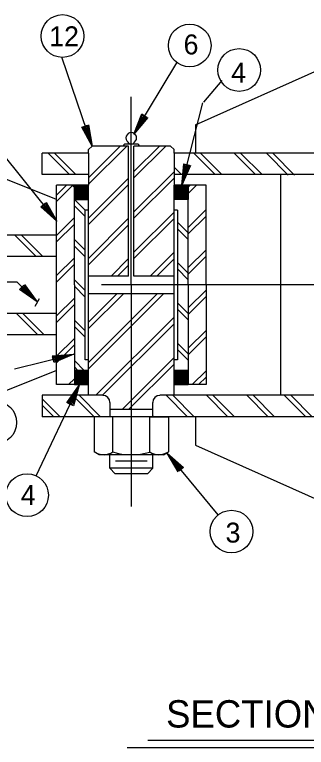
# Model space of a CAD drawing. Extents: x 0.1 to 13.5, y 0.1 to 9.5.
# Drawn here: x 7.902 to 8.756, y 5.682 to 7.825 of the extents above; entities that cross this region are included whole.
import ezdxf

# ---------------------------------------------------------------- set-up
doc = ezdxf.new("R2010")
doc.units = 0
for name, color, linetype in [('Level 2', 7, 'Continuous'), ('Level 25', 7, 'Continuous'), ('Level 3', 7, 'Continuous'), ('Level 50', 7, 'Continuous')]:
    doc.layers.add(name, color=color, linetype=linetype)

msp = doc.modelspace()

# ---------------------------------------------------------------- linework, layer by layer
at = {"layer": 'Level 2'}
for p, q in [((8.2434, 7.0344), (8.2434, 7.5849)), ((8.4309, 7.5031), (8.4309, 7.4198)), ((8.1288, 7.4406), (8.1184, 7.4302)), ((8.2356, 7.4406), (8.1288, 7.4406)), ((8.2202, 7.4406), (8.2202, 7.4416)), ((8.2624, 7.4458), (8.2244, 7.4458)), ((8.2356, 7.0604), (8.2356, 7.4406)), ((8.2434, 7.4458), (8.2434, 7.4458)), ((8.2434, 7.4458), (8.2434, 7.4458)), ((8.2512, 7.0604), (8.2512, 7.4406)), ((8.358, 7.4406), (8.2512, 7.4406)), ((8.2665, 7.4406), (8.2665, 7.4416)), ((8.358, 7.4406), (8.3684, 7.4302)), ((7.983, 7.3573), (7.983, 7.4198)), ((8.1184, 7.4198), (7.983, 7.4198)), ((8.1184, 7.4198), (8.1184, 7.4302)), ((8.1184, 7.4198), (8.1184, 7.3261)), ((8.3684, 7.4198), (8.3684, 7.4302)), ((8.3684, 7.4198), (8.3684, 7.3261)), ((9.0976, 7.4198), (8.3684, 7.4198)), ((8.1184, 7.3573), (7.983, 7.3573)), ((9.0976, 7.3573), (8.3684, 7.3573)), ((8.6809, 6.7115), (8.6809, 7.3573)), ((8.0247, 6.7427), (8.0247, 7.3261)), ((8.1184, 7.3261), (8.0247, 7.3261)), ((8.0768, 7.0344), (8.0768, 7.3261)), ((8.1184, 6.7115), (8.1184, 7.3261)), ((8.4622, 7.3261), (8.3684, 7.3261)), ((8.3684, 6.7115), (8.3684, 7.3261)), ((8.4101, 7.0344), (8.4101, 7.3261)), ((8.4622, 7.0344), (8.4622, 7.3261)), ((8.1184, 7.2844), (8.0768, 7.2844)), ((8.4101, 7.2844), (8.3684, 7.2844)), ((8.108, 6.8156), (8.108, 7.2531)), ((8.1184, 7.2531), (8.108, 7.2531)), ((8.3788, 7.2531), (8.3684, 7.2531)), ((8.3788, 7.2531), (8.3788, 6.8156)), ((8.0247, 7.1802), (7.4186, 7.1802)), ((8.0247, 7.1177), (7.4186, 7.1177)), ((8.2356, 7.0604), (8.1184, 7.0604)), ((8.3684, 7.0604), (8.2512, 7.0604)), ((8.0768, 7.0344), (8.0768, 6.7427)), ((10.1049, 7.0344), (8.1558, 7.0344)), ((8.2434, 7.0344), (8.2434, 6.3864)), ((8.4101, 7.0344), (8.4101, 6.7427)), ((8.4622, 7.0344), (8.4622, 6.7427)), ((8.3684, 7.0083), (8.1184, 7.0083)), ((8.0247, 6.9511), (7.4186, 6.9511)), ((8.0247, 6.8886), (7.4186, 6.8886)), ((8.1184, 6.8156), (8.108, 6.8156)), ((8.3788, 6.8156), (8.3684, 6.8156)), ((8.1184, 6.7844), (8.0768, 6.7844)), ((8.4101, 6.7844), (8.3684, 6.7844)), ((8.1184, 6.7427), (8.0247, 6.7427)), ((8.4622, 6.7427), (8.3684, 6.7427)), ((7.983, 6.7115), (7.983, 6.649)), ((8.1601, 6.7115), (7.983, 6.7115)), ((9.0976, 6.7115), (8.3268, 6.7115)), ((8.1809, 6.6906), (8.1809, 6.649)), ((8.3059, 6.6906), (8.3059, 6.649)), ((8.3059, 6.6698), (8.1809, 6.6698)), ((9.0976, 6.649), (7.983, 6.649)), ((8.3997, 6.649), (8.0872, 6.649)), ((8.1351, 6.649), (8.1351, 6.5461)), ((8.1892, 6.5459), (8.1892, 6.649)), ((8.2969, 6.649), (8.3518, 6.649)), ((8.2977, 6.5459), (8.2977, 6.649)), ((8.3518, 6.649), (8.3518, 6.5461)), ((8.4309, 6.649), (8.4309, 6.5656)), ((8.1496, 6.5377), (8.1351, 6.5461)), ((8.3373, 6.5377), (8.1496, 6.5377)), ((8.1807, 6.498), (8.1807, 6.5377)), ((8.3061, 6.498), (8.3061, 6.5377)), ((8.3373, 6.5377), (8.3518, 6.5461)), ((8.2903, 6.519), (8.197, 6.519)), ((8.1807, 6.498), (8.1963, 6.4823)), ((8.3061, 6.498), (8.1807, 6.498)), ((8.3061, 6.498), (8.2905, 6.4823)), ((8.2905, 6.4823), (8.1963, 6.4823)), ((8.2905, 6.4823), (8.1963, 6.4823)), ((8.2903, 6.4823), (8.197, 6.4823))]:
    msp.add_line(p, q, dxfattribs=at)
for points in [[(8.1184, 7.3289), (8.2302, 7.4406)], [(8.1184, 7.3478), (8.2113, 7.4406)], [(8.2512, 7.3473), (8.3446, 7.4406)], [(8.2512, 7.3662), (8.3257, 7.4406)], [(8.0624, 7.3573), (7.9999, 7.4198)], [(8.0812, 7.3573), (8.0187, 7.4198)], [(8.1184, 7.4191), (8.1177, 7.4198)], [(8.4892, 7.3573), (8.4267, 7.4198)], [(8.5081, 7.3573), (8.4456, 7.4198)], [(8.6071, 7.3573), (8.5446, 7.4198)], [(8.6259, 7.3573), (8.5634, 7.4198)], [(8.7024, 7.3559), (8.6399, 7.4184)], [(8.7024, 7.3559), (8.6399, 7.4184)], [(8.7212, 7.3559), (8.6587, 7.4184)], [(8.7212, 7.3559), (8.6587, 7.4184)], [(8.3902, 7.3573), (8.3684, 7.3791)], [(8.2512, 7.2483), (8.3684, 7.3655)], [(8.3714, 7.3573), (8.3684, 7.3602)], [(8.1184, 7.2299), (8.2356, 7.3471)], [(8.2512, 7.2295), (8.3684, 7.3467)], [(8.0247, 7.2783), (8.0724, 7.3261)], [(8.0247, 7.2972), (8.0536, 7.3261)], [(8.0768, 7.3193), (8.07, 7.3261)], [(8.0768, 7.3255), (8.1184, 7.3255)], [(8.0768, 7.3242), (8.1184, 7.3242)], [(8.0768, 7.323), (8.1184, 7.323)], [(8.0768, 7.3217), (8.1184, 7.3217)], [(8.0768, 7.3205), (8.1184, 7.3205)], [(8.0768, 7.3192), (8.1184, 7.3192)], [(8.0768, 7.318), (8.1184, 7.318)], [(8.0768, 7.3167), (8.1184, 7.3167)], [(8.0768, 7.3155), (8.1184, 7.3155)], [(8.0768, 7.3142), (8.1184, 7.3142)], [(8.0768, 7.313), (8.1184, 7.313)], [(8.0768, 7.3117), (8.1184, 7.3117)], [(8.0768, 7.3105), (8.1184, 7.3105)], [(8.0768, 7.3092), (8.1184, 7.3092)], [(8.0768, 7.308), (8.1184, 7.308)], [(8.1184, 7.211), (8.2356, 7.3282)], [(8.3684, 7.3255), (8.4101, 7.3255)], [(8.3684, 7.3243), (8.4101, 7.3243)], [(8.3684, 7.323), (8.4101, 7.323)], [(8.3684, 7.3218), (8.4101, 7.3218)], [(8.3684, 7.3205), (8.4101, 7.3205)], [(8.3684, 7.3193), (8.4101, 7.3193)], [(8.3684, 7.318), (8.4101, 7.318)], [(8.3684, 7.3168), (8.4101, 7.3168)], [(8.3684, 7.3155), (8.4101, 7.3155)], [(8.3684, 7.3143), (8.4101, 7.3143)], [(8.3684, 7.313), (8.4101, 7.313)], [(8.3684, 7.3118), (8.4101, 7.3118)], [(8.3684, 7.3105), (8.4101, 7.3105)], [(8.3684, 7.3093), (8.4101, 7.3093)], [(8.3684, 7.308), (8.4101, 7.308)], [(8.4101, 7.3018), (8.4344, 7.3261)], [(8.4101, 7.3206), (8.4155, 7.3261)], [(8.0768, 7.3067), (8.1184, 7.3067)], [(8.0768, 7.3055), (8.1184, 7.3055)], [(8.0768, 7.3042), (8.1184, 7.3042)], [(8.0768, 7.303), (8.1184, 7.303)], [(8.0768, 7.3017), (8.1184, 7.3017)], [(8.0768, 7.3005), (8.1184, 7.3005)], [(8.0768, 7.2992), (8.1184, 7.2992)], [(8.0768, 7.298), (8.1184, 7.298)], [(8.0768, 7.2967), (8.1184, 7.2967)], [(8.0768, 7.2955), (8.1184, 7.2955)], [(8.0768, 7.2942), (8.1184, 7.2942)], [(8.0768, 7.293), (8.1184, 7.293)], [(8.0768, 7.2917), (8.1184, 7.2917)], [(8.0768, 7.2905), (8.1184, 7.2905)], [(8.0768, 7.2892), (8.1184, 7.2892)], [(8.0768, 7.288), (8.1184, 7.288)], [(8.0768, 7.2867), (8.1184, 7.2867)], [(8.3684, 7.3068), (8.4101, 7.3068)], [(8.3684, 7.3055), (8.4101, 7.3055)], [(8.3684, 7.3043), (8.4101, 7.3043)], [(8.3684, 7.303), (8.4101, 7.303)], [(8.3684, 7.3018), (8.4101, 7.3018)], [(8.3684, 7.3005), (8.4101, 7.3005)], [(8.3684, 7.2993), (8.4101, 7.2993)], [(8.3684, 7.298), (8.4101, 7.298)], [(8.3684, 7.2968), (8.4101, 7.2968)], [(8.3684, 7.2955), (8.4101, 7.2955)], [(8.3684, 7.2943), (8.4101, 7.2943)], [(8.3684, 7.293), (8.4101, 7.293)], [(8.3684, 7.2918), (8.4101, 7.2918)], [(8.3684, 7.2905), (8.4101, 7.2905)], [(8.3684, 7.2893), (8.4101, 7.2893)], [(8.3684, 7.288), (8.4101, 7.288)], [(8.3684, 7.2868), (8.4101, 7.2868)], [(8.0768, 7.2855), (8.1184, 7.2855)], [(8.108, 7.2348), (8.0768, 7.266)], [(8.1085, 7.2531), (8.0772, 7.2844)], [(8.3684, 7.2855), (8.4101, 7.2855)], [(8.2512, 7.1305), (8.3684, 7.2477)], [(8.4101, 7.2028), (8.4622, 7.2549)], [(8.0247, 7.1793), (8.0768, 7.2314)], [(8.1184, 7.1121), (8.2356, 7.2292)], [(8.2512, 7.1116), (8.3684, 7.2288)], [(8.4101, 7.1839), (8.4622, 7.236)], [(8.0247, 7.1604), (8.0768, 7.2125)], [(8.1184, 7.0932), (8.2356, 7.2104)], [(8.4101, 7.1864), (8.3788, 7.2177)], [(7.9654, 7.1177), (7.9029, 7.1802)], [(7.9842, 7.1177), (7.9217, 7.1802)], [(8.4101, 7.1676), (8.3788, 7.1988)], [(8.108, 7.1358), (8.0768, 7.167)], [(8.108, 7.1169), (8.0768, 7.1481)], [(8.4101, 7.0849), (8.4622, 7.137)], [(8.299, 7.0604), (8.3684, 7.1298)], [(8.4101, 7.0661), (8.4622, 7.1182)], [(8.0247, 7.0615), (8.0768, 7.1136)], [(8.0247, 7.0426), (8.0768, 7.0947)], [(8.1847, 7.0604), (8.2356, 7.1114)], [(8.3179, 7.0604), (8.3684, 7.111)], [(8.4101, 7.0686), (8.3788, 7.0998)], [(8.2035, 7.0604), (8.2356, 7.0925)], [(8.4101, 7.0497), (8.3788, 7.081)], [(8.108, 7.0179), (8.0768, 7.0491)], [(8.108, 6.999), (8.0768, 7.0303)], [(8.1184, 6.7888), (8.3379, 7.0083)], [(8.1184, 6.9067), (8.2201, 7.0083)], [(8.1184, 6.8077), (8.3191, 7.0083)], [(8.1184, 6.9255), (8.2012, 7.0083)], [(8.4101, 6.9671), (8.4622, 7.0192)], [(8.0247, 6.9436), (8.0768, 6.9957)], [(8.4101, 6.9482), (8.4622, 7.0003)], [(8.0247, 6.9248), (8.0768, 6.9769)], [(8.4101, 6.9507), (8.3788, 6.982)], [(7.9697, 6.8886), (7.9072, 6.9511)], [(7.9886, 6.8886), (7.9261, 6.9511)], [(8.4101, 6.9319), (8.3788, 6.9631)], [(8.108, 6.9001), (8.0768, 6.9313)], [(8.1401, 6.7115), (8.3684, 6.9398)], [(8.108, 6.8812), (8.0768, 6.9124)], [(8.1589, 6.7115), (8.3684, 6.921)], [(8.4101, 6.8492), (8.4622, 6.9013)], [(8.4101, 6.8304), (8.4622, 6.8825)], [(8.0247, 6.8258), (8.0768, 6.8779)], [(8.0247, 6.8069), (8.0768, 6.859)], [(8.4101, 6.8329), (8.3788, 6.8641)], [(8.4101, 6.814), (8.3788, 6.8453)], [(8.2163, 6.6698), (8.3684, 6.822)], [(8.1058, 6.7844), (8.0768, 6.8134)], [(8.087, 6.7844), (8.0768, 6.7946)], [(8.2351, 6.6698), (8.3684, 6.8031)], [(8.0768, 6.7832), (8.1184, 6.7832)], [(8.0768, 6.7819), (8.1184, 6.7819)], [(8.0768, 6.7807), (8.1184, 6.7807)], [(8.0768, 6.7794), (8.1184, 6.7794)], [(8.0768, 6.7782), (8.1184, 6.7782)], [(8.0768, 6.7769), (8.1184, 6.7769)], [(8.0768, 6.7757), (8.1184, 6.7757)], [(8.0768, 6.7744), (8.1184, 6.7744)], [(8.0768, 6.7732), (8.1184, 6.7732)], [(8.3684, 6.7844), (8.4101, 6.7844)], [(8.3684, 6.7831), (8.4101, 6.7831)], [(8.3684, 6.7819), (8.4101, 6.7819)], [(8.3684, 6.7806), (8.4101, 6.7806)], [(8.3684, 6.7794), (8.4101, 6.7794)], [(8.3684, 6.7781), (8.4101, 6.7781)], [(8.3684, 6.7769), (8.4101, 6.7769)], [(8.3684, 6.7756), (8.4101, 6.7756)], [(8.3684, 6.7744), (8.4101, 6.7744)], [(8.3684, 6.7731), (8.4101, 6.7731)], [(8.4214, 6.7427), (8.4622, 6.7835)], [(8.0595, 6.7427), (8.0768, 6.76)], [(8.0768, 6.7719), (8.1184, 6.7719)], [(8.0768, 6.7707), (8.1184, 6.7707)], [(8.0768, 6.7694), (8.1184, 6.7694)], [(8.0768, 6.7682), (8.1184, 6.7682)], [(8.0768, 6.7669), (8.1184, 6.7669)], [(8.0768, 6.7657), (8.1184, 6.7657)], [(8.0768, 6.7644), (8.1184, 6.7644)], [(8.0768, 6.7632), (8.1184, 6.7632)], [(8.0768, 6.7619), (8.1184, 6.7619)], [(8.0768, 6.7607), (8.1184, 6.7607)], [(8.0768, 6.7594), (8.1184, 6.7594)], [(8.0768, 6.7582), (8.1184, 6.7582)], [(8.0768, 6.7569), (8.1184, 6.7569)], [(8.0768, 6.7557), (8.1184, 6.7557)], [(8.0768, 6.7544), (8.1184, 6.7544)], [(8.0768, 6.7532), (8.1184, 6.7532)], [(8.0768, 6.7519), (8.1184, 6.7519)], [(8.0768, 6.7507), (8.1184, 6.7507)], [(8.3684, 6.7719), (8.4101, 6.7719)], [(8.3684, 6.7706), (8.4101, 6.7706)], [(8.3684, 6.7694), (8.4101, 6.7694)], [(8.3684, 6.7681), (8.4101, 6.7681)], [(8.3684, 6.7669), (8.4101, 6.7669)], [(8.3684, 6.7656), (8.4101, 6.7656)], [(8.3684, 6.7644), (8.4101, 6.7644)], [(8.3684, 6.7631), (8.4101, 6.7631)], [(8.3684, 6.7619), (8.4101, 6.7619)], [(8.3684, 6.7606), (8.4101, 6.7606)], [(8.3684, 6.7594), (8.4101, 6.7594)], [(8.3684, 6.7581), (8.4101, 6.7581)], [(8.3684, 6.7569), (8.4101, 6.7569)], [(8.3684, 6.7556), (8.4101, 6.7556)], [(8.3684, 6.7544), (8.4101, 6.7544)], [(8.3684, 6.7531), (8.4101, 6.7531)], [(8.3684, 6.7519), (8.4101, 6.7519)], [(8.4403, 6.7427), (8.4622, 6.7646)], [(8.0768, 6.7494), (8.1184, 6.7494)], [(8.0768, 6.7482), (8.1184, 6.7482)], [(8.0768, 6.7469), (8.1184, 6.7469)], [(8.0768, 6.7457), (8.1184, 6.7457)], [(8.0768, 6.7444), (8.1184, 6.7444)], [(8.0768, 6.7432), (8.1184, 6.7432)], [(8.3684, 6.7506), (8.4101, 6.7506)], [(8.3684, 6.7494), (8.4101, 6.7494)], [(8.3684, 6.7481), (8.4101, 6.7481)], [(8.3684, 6.7469), (8.4101, 6.7469)], [(8.3684, 6.7456), (8.4101, 6.7456)], [(8.3684, 6.7444), (8.4101, 6.7444)], [(8.3684, 6.7431), (8.4101, 6.7431)], [(8.1343, 6.649), (8.0718, 6.7115)], [(8.1531, 6.649), (8.0906, 6.7115)], [(8.4083, 6.649), (8.3458, 6.7115)], [(8.4272, 6.649), (8.3647, 6.7115)], [(8.5262, 6.649), (8.4637, 6.7115)], [(8.545, 6.649), (8.4825, 6.7115)], [(8.644, 6.649), (8.5815, 6.7115)], [(8.6629, 6.649), (8.6004, 6.7115)], [(8.7537, 6.649), (8.6912, 6.7115)], [(8.7725, 6.649), (8.71, 6.7115)], [(8.0353, 6.649), (7.983, 6.7012)], [(8.0164, 6.649), (7.983, 6.6824)], [(8.3093, 6.649), (8.3059, 6.6524)]]:
    msp.add_lwpolyline(points, dxfattribs=at)
for points in [[(8.0768, 7.3261), (8.0768, 7.2844), (8.1184, 7.2844), (8.1184, 7.3261)], [(8.4101, 7.3261), (8.4101, 7.2844), (8.3684, 7.2844), (8.3684, 7.3261)], [(8.0768, 6.7844), (8.0768, 6.7427), (8.1184, 6.7427), (8.1184, 6.7844)], [(8.3684, 6.7844), (8.3684, 6.7427), (8.4101, 6.7427), (8.4101, 6.7844)]]:
    msp.add_lwpolyline(points, close=True, dxfattribs=at)
for centre, radius, start, end in [((8.2434, 7.4645), 0.0156, 306.8699, 233.1301), ((8.2244, 7.4416), 0.00417, 90, 180), ((8.2278, 7.4437), 0.0104, 11.771, 53.1301), ((8.2591, 7.4437), 0.0104, 126.8699, 168.229), ((8.2624, 7.4416), 0.00417, 0, 90), ((8.1601, 6.6906), 0.0208, 0, 90), ((8.3268, 6.6906), 0.0208, 90, 180), ((8.1625, 6.5847), 0.047, 239.7124, 304.511), ((8.2441, 6.7259), 0.1882, 253.0184, 286.4966), ((8.3243, 6.5847), 0.047, 235.489, 300.2876)]:
    msp.add_arc(centre, radius, start, end, dxfattribs=at)
at = {"layer": 'Level 25'}
for p, q in [((8.4309, 7.5031), (9.0143, 7.7636)), ((8.4554, 7.5694), (8.5091, 7.632)), ((8.0247, 7.2844), (7.502, 7.4927)), ((8.0256, 7.2212), (7.8111, 7.4878)), ((8.0247, 6.7844), (7.502, 6.5761)), ((8.4309, 6.5656), (9.0143, 6.3052))]:
    msp.add_line(p, q, dxfattribs=at)
at = {"layer": 'Level 3'}
for p, q in [((8.1288, 7.4406), (8.0397, 7.7006)), ((8.2509, 7.4758), (8.3766, 7.6843)), ((8.3913, 7.326), (8.4532, 7.5668)), ((8.2598, 7.4906), (8.2598, 7.4906)), ((8.2509, 7.4758), (8.2509, 7.4758)), ((8.1232, 7.457), (8.1232, 7.457)), ((8.1288, 7.4406), (8.1288, 7.4406)), ((8.3956, 7.3428), (8.3956, 7.3428)), ((8.3913, 7.326), (8.3913, 7.326)), ((7.8612, 7.0436), (7.9082, 7.0436)), ((7.9082, 7.0436), (7.9684, 6.9853)), ((7.956, 6.9974), (7.956, 6.9974)), ((7.9622, 6.9718), (7.9747, 6.9947)), ((7.9684, 6.9853), (7.9684, 6.9853)), ((7.9012, 6.7892), (8.0753, 6.8321)), ((7.9652, 6.4757), (8.0912, 6.7415)), ((8.0912, 6.7415), (8.0912, 6.7415)), ((8.0838, 6.7258), (8.0838, 6.7258)), ((8.4978, 6.362), (8.3485, 6.5421)), ((8.3485, 6.5421), (8.3485, 6.5421)), ((8.3595, 6.5287), (8.3595, 6.5287)), ((8.2917, 5.7027), (8.9163, 5.7027)), ((8.2312, 5.6819), (8.9561, 5.6819))]:
    msp.add_line(p, q, dxfattribs=at)
for points in [[(8.2919, 7.5238), (8.2509, 7.4758), (8.2742, 7.5345), (8.2893, 7.5254), (8.2598, 7.4906), (8.2757, 7.5305), (8.2854, 7.5246), (8.2684, 7.5049), (8.2772, 7.5265), (8.2812, 7.5241), (8.2774, 7.5197)], [(8.1184, 7.5029), (8.1288, 7.4406), (8.0988, 7.4962), (8.1156, 7.502), (8.1232, 7.457), (8.1029, 7.4948), (8.1136, 7.4985), (8.1178, 7.4728), (8.1069, 7.4934), (8.1113, 7.4949), (8.1122, 7.4892)], [(8.4168, 7.3838), (8.3913, 7.326), (8.3968, 7.389), (8.4139, 7.3846), (8.3956, 7.3428), (8.3993, 7.3856), (8.4103, 7.3827), (8.3997, 7.359), (8.4019, 7.3821), (8.4064, 7.381), (8.404, 7.3757)], [(7.9308, 7.0361), (7.9684, 6.9853), (7.9164, 7.0212), (7.9287, 7.0339), (7.956, 6.9974), (7.9207, 7.0218), (7.9286, 7.0299), (7.944, 7.009), (7.9249, 7.0223), (7.9281, 7.0257), (7.9315, 7.021)], [(8.0552, 6.6896), (8.0912, 6.7415), (8.0738, 6.6807), (8.0579, 6.6883), (8.0838, 6.7258), (8.072, 6.6846), (8.0617, 6.6894), (8.0766, 6.7108), (8.0701, 6.6884), (8.0659, 6.6904), (8.0692, 6.6951)], [(8.3803, 6.4875), (8.3485, 6.5421), (8.3962, 6.5007), (8.3826, 6.4894), (8.3595, 6.5287), (8.3919, 6.5006), (8.3832, 6.4934), (8.3702, 6.5159), (8.3877, 6.5005), (8.3841, 6.4976), (8.3812, 6.5026)]]:
    msp.add_lwpolyline(points, dxfattribs=at)
for centre in [(8.0421, 7.7624), (8.4143, 7.7347), (8.5593, 7.663), (7.8454, 6.6319), (7.9384, 6.4193), (8.5365, 6.3129)]:
    msp.add_circle(centre, 0.0625, dxfattribs=at)
at = {"layer": 'Level 50'}
for p, q in [((8.0147, 7.2347), (8.0147, 7.2347)), ((8.0256, 7.2212), (8.0256, 7.2212)), ((8.0585, 6.828), (8.0585, 6.828)), ((8.0753, 6.8321), (8.0753, 6.8321))]:
    msp.add_line(p, q, dxfattribs=at)
for points in [[(7.9945, 7.2763), (8.0256, 7.2212), (7.9784, 7.2633), (7.9922, 7.2744), (8.0147, 7.2347), (7.9827, 7.2633), (7.9915, 7.2704), (8.0043, 7.2477), (7.987, 7.2633), (7.9906, 7.2663), (7.9934, 7.2612)], [(8.0123, 6.8273), (8.0753, 6.8321), (8.0173, 6.8072), (8.0131, 6.8243), (8.0585, 6.828), (8.0191, 6.8111), (8.0164, 6.8221), (8.0423, 6.824), (8.0209, 6.8149), (8.0198, 6.8195), (8.0255, 6.8199)]]:
    msp.add_lwpolyline(points, dxfattribs=at)

# ---------------------------------------------------------------- texts
at = {"layer": 'Level 3'}
for s, height, p in [('12', 0.05833, (8.0033, 7.7324)), ('6', 0.0583, (8.3965, 7.7087)), ('4', 0.0583, (8.5358, 7.6264)), ('4', 0.0583, (7.92, 6.3908)), ('3', 0.0583, (8.5194, 6.2808)), ('SECTION  A', 0.08, (8.3452, 5.7398))]:
    msp.add_text(s, height=height, dxfattribs=at).set_placement(p)

doc.saveas('drawing.dxf')
